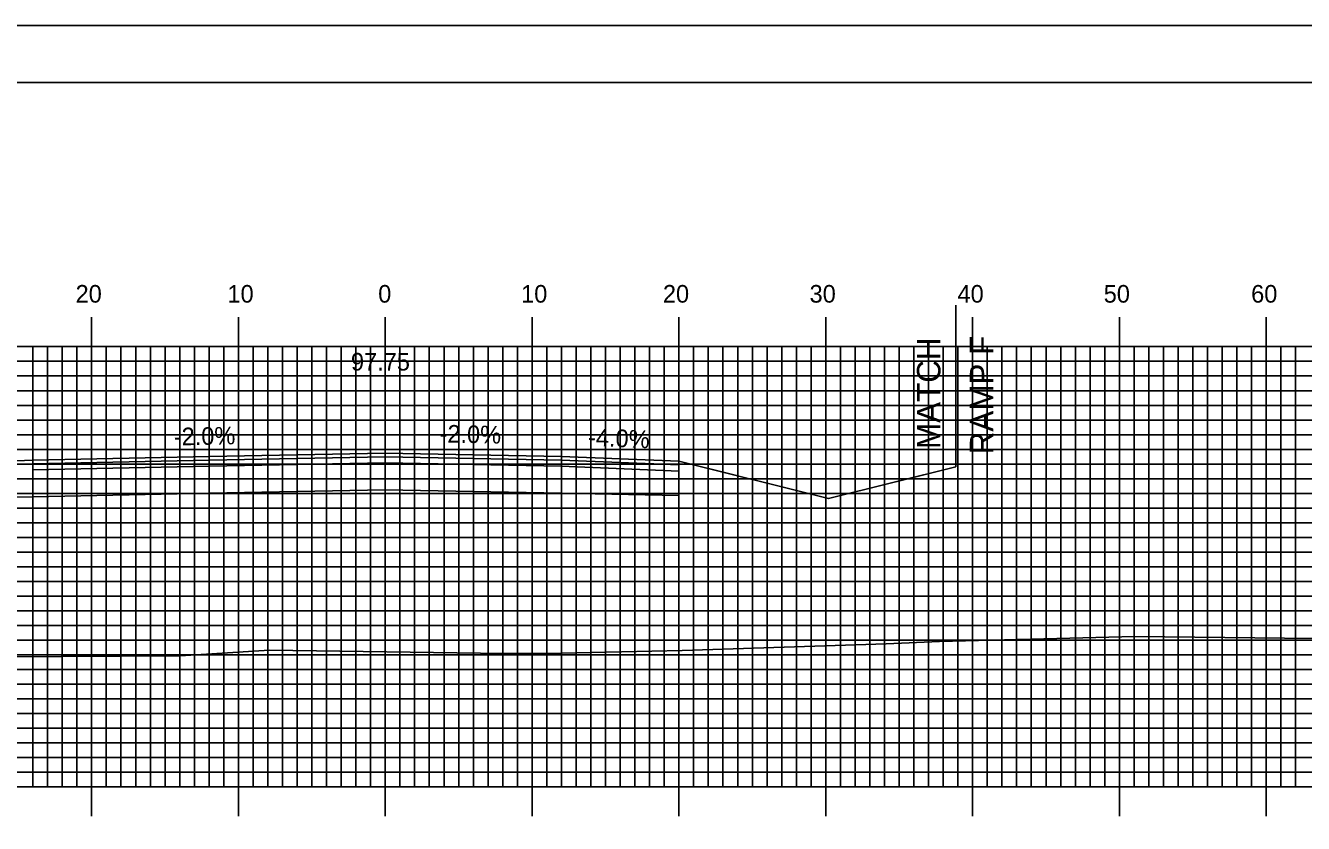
# Model space of a CAD drawing. Extents: x 1757856 to 1758199, y 442591 to 442811.
# Drawn here: x 1757997.1 to 1758084.2, y 442756.2 to 442810.5 of the extents above; entities that cross this region are included whole.
import ezdxf

# ---------------------------------------------------------------- set-up
doc = ezdxf.new("R2010")
doc.units = 0
for name, color, linetype in [('ANNOTATION', 7, 'Continuous'), ('BORDER', 7, 'Continuous'), ('D_Roadway_Centerline', 7, 'Continuous'), ('D_Roadway_Centerline_Text', 7, 'Continuous'), ('D_Roadway_Edge_Shoulder', 7, 'Continuous'), ('D_Roadway_Edge_TW', 7, 'Continuous'), ('D_Roadway_Pavement', 7, 'Continuous'), ('D_Roadway_SubGrade', 7, 'Continuous'), ('H_V ANNOTATION', 7, 'Continuous'), ('MAJOR', 7, 'Continuous'), ('MINOR', 7, 'Continuous'), ('PLOT BOUNDARY', 7, 'Continuous'), ('S_Roadway_Centerline', 7, 'Continuous')]:
    doc.layers.add(name, color=color, linetype=linetype)

msp = doc.modelspace()

# ---------------------------------------------------------------- linework, layer by layer
at = {"layer": 'BORDER'}
msp.add_lwpolyline([(1757872.022, 442596.665), (1758192.022, 442596.665), (1758192.022, 442806.665), (1757872.022, 442806.665)], close=True, dxfattribs=at)
at = {"layer": 'D_Roadway_Centerline'}
msp.add_lwpolyline([(1757944.654, 442766.626), (1757977.622, 442777.616), (1757979.448, 442778.072), (1757989.622, 442780.616), (1757997.622, 442780.936), (1758009.622, 442781.176), (1758021.622, 442781.416), (1758033.622, 442781.176), (1758041.622, 442780.856), (1758051.806, 442778.31), (1758060.481, 442780.479)], dxfattribs=at)
at = {"layer": 'D_Roadway_Edge_Shoulder'}
for points in [[(1757997.622, 442780.936), (1757989.622, 442780.616), (1757989.622, 442780.366), (1757997.622, 442780.686)], [(1758033.622, 442781.176), (1758041.622, 442780.856), (1758041.622, 442780.606), (1758033.622, 442780.926)]]:
    msp.add_lwpolyline(points, close=True, dxfattribs=at)
at = {"layer": 'D_Roadway_Edge_TW'}
for points in [[(1758009.622, 442780.926), (1758009.622, 442781.176), (1758021.622, 442781.416), (1758033.622, 442781.176), (1758033.622, 442780.926), (1758021.622, 442781.166)], [(1758009.622, 442781.176), (1757997.622, 442780.936), (1757997.622, 442780.686), (1758009.622, 442780.926)]]:
    msp.add_lwpolyline(points, close=True, dxfattribs=at)
msp.add_lwpolyline([(1758009.622, 442781.176), (1758009.622, 442780.926)], dxfattribs=at)
at = {"layer": 'D_Roadway_Pavement'}
for points in [[(1758009.622, 442780.926), (1757997.622, 442780.686), (1757997.622, 442780.269), (1758009.622, 442780.509)], [(1758009.622, 442780.509), (1758009.622, 442780.926), (1758021.622, 442781.166), (1758033.622, 442780.926), (1758033.622, 442780.509), (1758021.622, 442780.749)], [(1758033.622, 442780.926), (1758041.622, 442780.606), (1758041.622, 442780.189), (1758033.622, 442780.509)]]:
    msp.add_lwpolyline(points, close=True, dxfattribs=at)
for points in [[(1757997.622, 442780.686), (1757997.622, 442780.269)], [(1758009.622, 442780.926), (1758009.622, 442780.509)], [(1758009.622, 442780.926), (1758009.622, 442780.509)]]:
    msp.add_lwpolyline(points, dxfattribs=at)
at = {"layer": 'D_Roadway_SubGrade'}
for p, q in [((1758060.481, 442791.49), (1758060.481, 442780.479)), ((1758060.481, 442780.479), (1758060.481, 442783.049)), ((1758041.622, 442780.856), (1758045.622, 442779.856)), ((1758060.481, 442780.479), (1758056.481, 442779.479))]:
    msp.add_line(p, q, dxfattribs=at)
for points in [[(1757997.622, 442780.269), (1757997.622, 442780.686), (1757989.622, 442780.366), (1757989.622, 442780.616), (1757979.448, 442778.072), (1757997.622, 442778.436)], [(1758009.622, 442780.509), (1757997.622, 442780.269), (1757997.622, 442778.436), (1758009.622, 442778.676)], [(1758009.622, 442778.676), (1758009.622, 442780.509), (1758021.622, 442780.749), (1758033.622, 442780.509), (1758033.622, 442778.676), (1758021.622, 442778.916)], [(1758033.622, 442780.509), (1758041.622, 442780.189), (1758041.622, 442780.606), (1758041.622, 442780.856), (1758041.622, 442778.516), (1758033.622, 442778.676)]]:
    msp.add_lwpolyline(points, close=True, dxfattribs=at)
msp.add_lwpolyline([(1758009.622, 442780.509), (1758009.622, 442778.676)], dxfattribs=at)
at = {"layer": 'MAJOR'}
for p, q in [((1758001.622, 442790.669), (1758001.622, 442788.665)), ((1758011.622, 442790.669), (1758011.622, 442788.665)), ((1758021.622, 442790.669), (1758021.622, 442788.665)), ((1758031.622, 442790.669), (1758031.622, 442788.665)), ((1758041.622, 442790.669), (1758041.622, 442788.665)), ((1758051.622, 442790.669), (1758051.622, 442788.665)), ((1758061.622, 442790.669), (1758061.622, 442788.665)), ((1758071.622, 442790.669), (1758071.622, 442788.665)), ((1758081.622, 442790.669), (1758081.622, 442788.665)), ((1757881.622, 442788.665), (1758161.622, 442788.665)), ((1757881.622, 442788.665), (1758161.622, 442788.665)), ((1758001.622, 442758.665), (1758001.622, 442788.665)), ((1758011.622, 442758.665), (1758011.622, 442788.665)), ((1758021.622, 442758.665), (1758021.622, 442788.665)), ((1758031.622, 442758.665), (1758031.622, 442788.665)), ((1758041.622, 442758.665), (1758041.622, 442788.665)), ((1758051.622, 442758.665), (1758051.622, 442788.665)), ((1758061.622, 442758.665), (1758061.622, 442788.665)), ((1758071.622, 442758.665), (1758071.622, 442788.665)), ((1758081.622, 442758.665), (1758081.622, 442788.665)), ((1757881.622, 442783.665), (1758161.622, 442783.665)), ((1757881.622, 442778.665), (1758161.622, 442778.665)), ((1757881.622, 442773.665), (1758161.622, 442773.665)), ((1757881.622, 442768.665), (1758161.622, 442768.665)), ((1757881.622, 442763.665), (1758161.622, 442763.665)), ((1757881.622, 442758.665), (1758161.622, 442758.665)), ((1757881.622, 442758.665), (1758161.622, 442758.665)), ((1758001.622, 442756.661), (1758001.622, 442758.665)), ((1758011.622, 442756.661), (1758011.622, 442758.665)), ((1758021.622, 442756.661), (1758021.622, 442758.665)), ((1758031.622, 442756.661), (1758031.622, 442758.665)), ((1758041.622, 442756.661), (1758041.622, 442758.665)), ((1758051.622, 442756.661), (1758051.622, 442758.665)), ((1758061.622, 442756.661), (1758061.622, 442758.665)), ((1758071.622, 442756.661), (1758071.622, 442758.665)), ((1758081.622, 442756.661), (1758081.622, 442758.665))]:
    msp.add_line(p, q, dxfattribs=at)
at = {"layer": 'MINOR'}
for p, q in [((1757997.622, 442758.665), (1757997.622, 442788.665)), ((1757998.622, 442758.665), (1757998.622, 442788.665)), ((1757999.622, 442758.665), (1757999.622, 442788.665)), ((1758000.622, 442758.665), (1758000.622, 442788.665)), ((1758002.622, 442758.665), (1758002.622, 442788.665)), ((1758003.622, 442758.665), (1758003.622, 442788.665)), ((1758004.622, 442758.665), (1758004.622, 442788.665)), ((1758005.622, 442758.665), (1758005.622, 442788.665)), ((1758006.622, 442758.665), (1758006.622, 442788.665)), ((1758007.622, 442758.665), (1758007.622, 442788.665)), ((1758008.622, 442758.665), (1758008.622, 442788.665)), ((1758009.622, 442758.665), (1758009.622, 442788.665)), ((1758010.622, 442758.665), (1758010.622, 442788.665)), ((1758012.622, 442758.665), (1758012.622, 442788.665)), ((1758013.622, 442758.665), (1758013.622, 442788.665)), ((1758014.622, 442758.665), (1758014.622, 442788.665)), ((1758015.622, 442758.665), (1758015.622, 442788.665)), ((1758016.622, 442758.665), (1758016.622, 442788.665)), ((1758017.622, 442758.665), (1758017.622, 442788.665)), ((1758018.622, 442758.665), (1758018.622, 442788.665)), ((1758019.622, 442758.665), (1758019.622, 442788.665)), ((1758020.622, 442758.665), (1758020.622, 442788.665)), ((1758022.622, 442758.665), (1758022.622, 442788.665)), ((1758023.622, 442758.665), (1758023.622, 442788.665)), ((1758024.622, 442758.665), (1758024.622, 442788.665)), ((1758025.622, 442758.665), (1758025.622, 442788.665)), ((1758026.622, 442758.665), (1758026.622, 442788.665)), ((1758027.622, 442758.665), (1758027.622, 442788.665)), ((1758028.622, 442758.665), (1758028.622, 442788.665)), ((1758029.622, 442758.665), (1758029.622, 442788.665)), ((1758030.622, 442758.665), (1758030.622, 442788.665)), ((1758032.622, 442758.665), (1758032.622, 442788.665)), ((1758033.622, 442758.665), (1758033.622, 442788.665)), ((1758034.622, 442758.665), (1758034.622, 442788.665)), ((1758035.622, 442758.665), (1758035.622, 442788.665)), ((1758036.622, 442758.665), (1758036.622, 442788.665)), ((1758037.622, 442758.665), (1758037.622, 442788.665)), ((1758038.622, 442758.665), (1758038.622, 442788.665)), ((1758039.622, 442758.665), (1758039.622, 442788.665)), ((1758040.622, 442758.665), (1758040.622, 442788.665)), ((1758042.622, 442758.665), (1758042.622, 442788.665)), ((1758043.622, 442758.665), (1758043.622, 442788.665)), ((1758044.622, 442758.665), (1758044.622, 442788.665)), ((1758045.622, 442758.665), (1758045.622, 442788.665)), ((1758046.622, 442758.665), (1758046.622, 442788.665)), ((1758047.622, 442758.665), (1758047.622, 442788.665)), ((1758048.622, 442758.665), (1758048.622, 442788.665)), ((1758049.622, 442758.665), (1758049.622, 442788.665)), ((1758050.622, 442758.665), (1758050.622, 442788.665)), ((1758052.622, 442758.665), (1758052.622, 442788.665)), ((1758053.622, 442758.665), (1758053.622, 442788.665)), ((1758054.622, 442758.665), (1758054.622, 442788.665)), ((1758055.622, 442758.665), (1758055.622, 442788.665)), ((1758056.622, 442758.665), (1758056.622, 442788.665)), ((1758057.622, 442758.665), (1758057.622, 442788.665)), ((1758058.622, 442758.665), (1758058.622, 442788.665)), ((1758059.622, 442758.665), (1758059.622, 442788.665)), ((1758060.622, 442758.665), (1758060.622, 442788.665)), ((1758062.622, 442758.665), (1758062.622, 442788.665)), ((1758063.622, 442758.665), (1758063.622, 442788.665)), ((1758064.622, 442758.665), (1758064.622, 442788.665)), ((1758065.622, 442758.665), (1758065.622, 442788.665)), ((1758066.622, 442758.665), (1758066.622, 442788.665)), ((1758067.622, 442758.665), (1758067.622, 442788.665)), ((1758068.622, 442758.665), (1758068.622, 442788.665)), ((1758069.622, 442758.665), (1758069.622, 442788.665)), ((1758070.622, 442758.665), (1758070.622, 442788.665)), ((1758072.622, 442758.665), (1758072.622, 442788.665)), ((1758073.622, 442758.665), (1758073.622, 442788.665)), ((1758074.622, 442758.665), (1758074.622, 442788.665)), ((1758075.622, 442758.665), (1758075.622, 442788.665)), ((1758076.622, 442758.665), (1758076.622, 442788.665)), ((1758077.622, 442758.665), (1758077.622, 442788.665)), ((1758078.622, 442758.665), (1758078.622, 442788.665)), ((1758079.622, 442758.665), (1758079.622, 442788.665)), ((1758080.622, 442758.665), (1758080.622, 442788.665)), ((1758082.622, 442758.665), (1758082.622, 442788.665)), ((1758083.622, 442758.665), (1758083.622, 442788.665)), ((1757881.622, 442787.665), (1758161.622, 442787.665)), ((1757881.622, 442786.665), (1758161.622, 442786.665)), ((1757881.622, 442785.665), (1758161.622, 442785.665)), ((1757881.622, 442784.665), (1758161.622, 442784.665)), ((1757881.622, 442782.665), (1758161.622, 442782.665)), ((1757881.622, 442781.665), (1758161.622, 442781.665)), ((1757881.622, 442780.665), (1758161.622, 442780.665)), ((1757881.622, 442779.665), (1758161.622, 442779.665)), ((1757881.622, 442777.665), (1758161.622, 442777.665)), ((1757881.622, 442776.665), (1758161.622, 442776.665)), ((1757881.622, 442775.665), (1758161.622, 442775.665)), ((1757881.622, 442774.665), (1758161.622, 442774.665)), ((1757881.622, 442772.665), (1758161.622, 442772.665)), ((1757881.622, 442771.665), (1758161.622, 442771.665)), ((1757881.622, 442770.665), (1758161.622, 442770.665)), ((1757881.622, 442769.665), (1758161.622, 442769.665)), ((1757881.622, 442767.665), (1758161.622, 442767.665)), ((1757881.622, 442766.665), (1758161.622, 442766.665)), ((1757881.622, 442765.665), (1758161.622, 442765.665)), ((1757881.622, 442764.665), (1758161.622, 442764.665)), ((1757881.622, 442762.665), (1758161.622, 442762.665)), ((1757881.622, 442761.665), (1758161.622, 442761.665)), ((1757881.622, 442760.665), (1758161.622, 442760.665)), ((1757881.622, 442759.665), (1758161.622, 442759.665))]:
    msp.add_line(p, q, dxfattribs=at)
at = {"layer": 'PLOT BOUNDARY'}
msp.add_lwpolyline([(1757855.835, 442590.547), (1758195.835, 442590.547), (1758195.835, 442810.547), (1757855.835, 442810.547)], close=True, dxfattribs=at)
at = {"layer": 'S_Roadway_Centerline'}
msp.add_lwpolyline([(1757942.939, 442766.635), (1757957.701, 442766.558), (1757965.118, 442766.762), (1757976.564, 442767.11), (1757994.443, 442767.499), (1757995.023, 442767.519), (1757995.513, 442767.52), (1758007.657, 442767.599), (1758013.741, 442767.973), (1758029.704, 442767.746), (1758033.585, 442767.778), (1758041.833, 442767.951), (1758055.74, 442768.406), (1758059.357, 442768.581), (1758072.666, 442768.912), (1758091.047, 442768.717)], dxfattribs=at)

# ---------------------------------------------------------------- texts
at = {"layer": 'ANNOTATION'}
for s, height, rotation, p in [('MATCH', 1.6, 90, (1758059.434, 442781.687)), ('RAMP F', 1.6, 90, (1758063.034, 442781.326)), ('-2.0%', 1.2, 1.14576, (1758007.228, 442781.928)), ('-2.0%', 1.2, 358.85424, (1758025.308, 442782.142)), ('-4.0%', 1.2, 357.70939, (1758035.414, 442781.906))]:
    msp.add_text(s, height=height, rotation=rotation, dxfattribs=at).set_placement(p)
at = {"layer": 'D_Roadway_Centerline'}
for s, p in [('C', (1758021.617, 442781.416)), ('L', (1758021.622, 442781.408))]:
    msp.add_text(s, height=0.0146, dxfattribs=at).set_placement(p)
at = {"layer": 'D_Roadway_Centerline_Text'}
msp.add_text('97.75', height=1.2, dxfattribs=at).set_placement((1758019.284, 442787.037))
at = {"layer": 'H_V ANNOTATION'}
for s, p in [('20', (1758000.53, 442791.665)), ('10', (1758010.873, 442791.665)), ('0', (1758021.14, 442791.665)), ('10', (1758030.873, 442791.665)), ('20', (1758040.53, 442791.665)), ('30', (1758050.52, 442791.665)), ('40', (1758060.594, 442791.665)), ('50', (1758070.552, 442791.665)), ('60', (1758080.594, 442791.665))]:
    msp.add_text(s, height=1.2, dxfattribs=at).set_placement(p)

doc.saveas('drawing.dxf')
